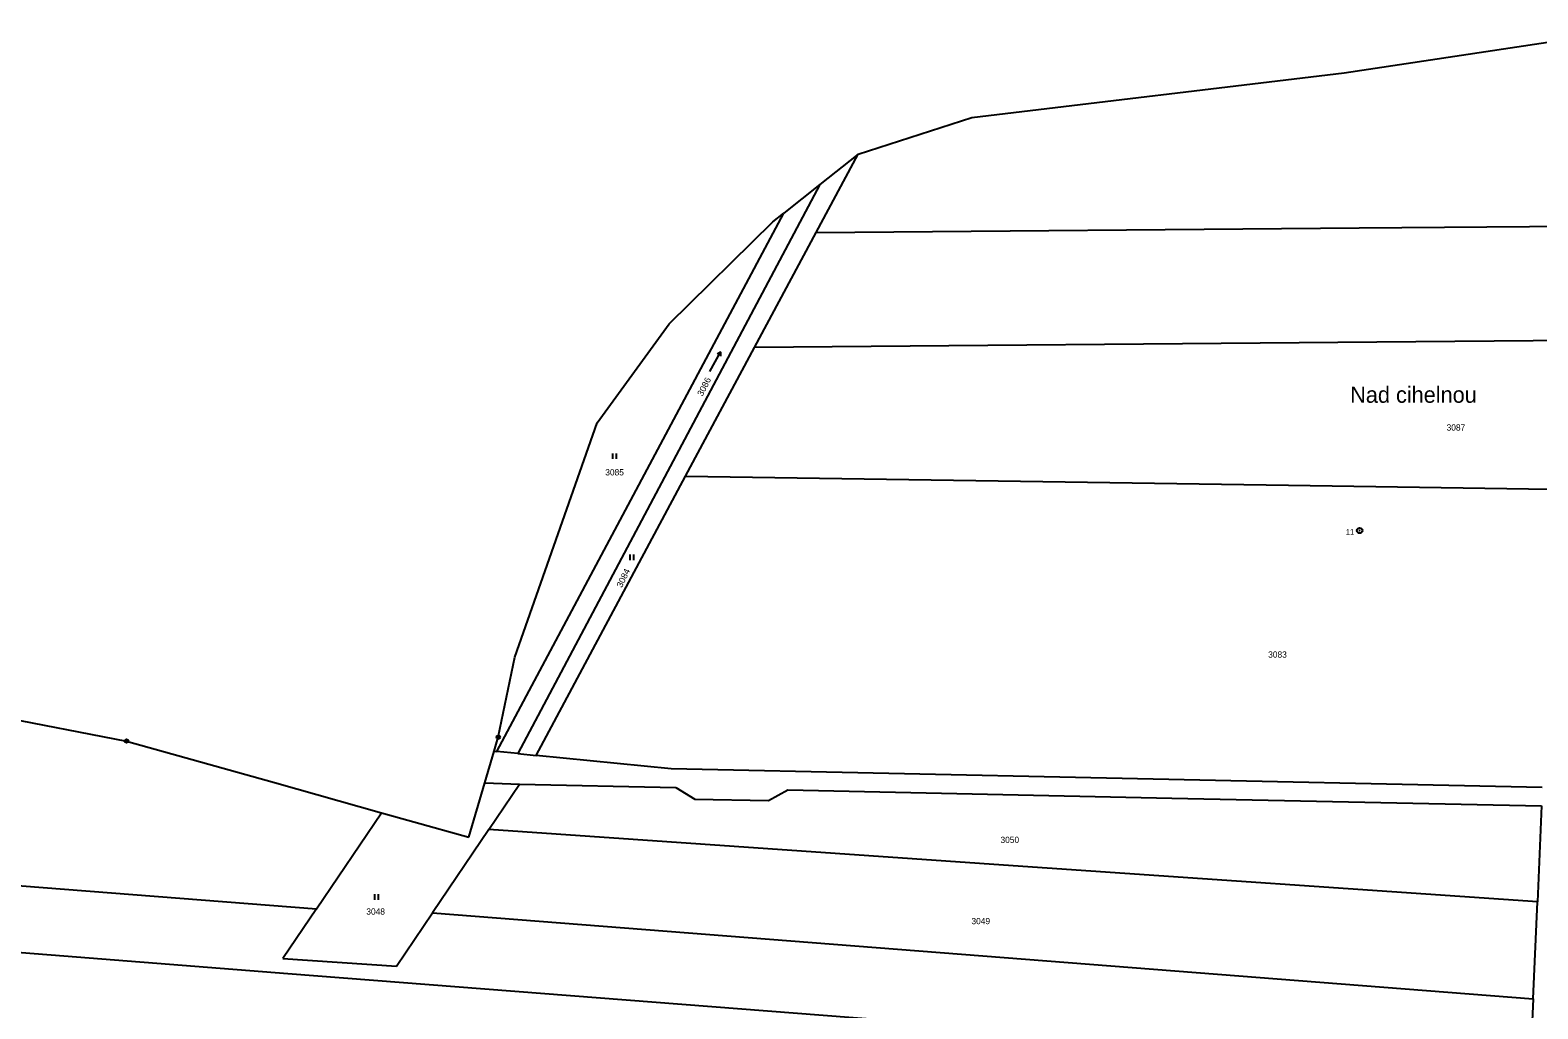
# Model space of a CAD drawing. Extents: x -618848 to -615803, y -1044450 to -1042254.
# Drawn here: x -617807.4 to -617398.4, y -1042588.2 to -1042322.9 of the extents above; entities that cross this region are included whole.
import ezdxf
from ezdxf.enums import TextEntityAlignment as Align

# ---------------------------------------------------------------- set-up
doc = ezdxf.new("R2010")
doc.units = 0
doc.header["$LTSCALE"] = 0.68
for name, color, linetype, lineweight in [('1', 7, 'Continuous', 25), ('3', 7, 'Continuous', 25), ('7', 7, 'Continuous', 13), ('8', 7, 'Continuous', 25)]:
    doc.layers.add(name, color=color, linetype=linetype, lineweight=lineweight)
doc.layers.add('2', color=7, linetype='Continuous')

msp = doc.modelspace()

# ---------------------------------------------------------------- linework, layer by layer
at = {"layer": '1'}
for p, q in [((-617450.93, -1042334.49), (-617374.17, -1042322.92)), ((-617551.92, -1042346.63), (-617450.93, -1042334.49)), ((-617582.79, -1042356.53), (-617551.92, -1042346.63)), ((-617594.16, -1042377.76), (-617582.79, -1042356.53)), ((-617582.79, -1042356.53), (-617593.16, -1042364.75)), ((-617593.16, -1042364.75), (-617675.07, -1042519.03)), ((-617593.16, -1042364.75), (-617602.93, -1042372.5)), ((-617680.74, -1042518.47), (-617602.93, -1042372.5)), ((-617634.06, -1042402.53), (-617605.92, -1042374.87)), ((-617605.92, -1042374.87), (-617602.93, -1042372.5)), ((-617446.82, -1042376.54), (-617299.47, -1042375.32)), ((-617610.87, -1042408.95), (-617594.16, -1042377.76)), ((-617594.16, -1042377.76), (-617446.82, -1042376.54)), ((-617653.53, -1042429.4), (-617634.06, -1042402.53)), ((-617442.07, -1042407.54), (-617610.87, -1042408.95)), ((-617273.27, -1042406.12), (-617442.07, -1042407.54)), ((-617629.57, -1042443.86), (-617610.87, -1042408.95)), ((-617675.87, -1042492.93), (-617653.53, -1042429.4)), ((-617670.1, -1042519.53), (-617629.57, -1042443.86)), ((-617629.57, -1042443.86), (-617465.98, -1042446.3)), ((-617465.98, -1042446.3), (-617302.39, -1042448.75)), ((-617680.4, -1042514.61), (-617675.87, -1042492.93)), ((-617817.51, -1042508.69), (-617781.23, -1042515.64)), ((-617681.51, -1042518.39), (-617680.4, -1042514.61)), ((-617781.23, -1042515.64), (-617741.09, -1042526.93)), ((-617684.03, -1042526.99), (-617681.51, -1042518.39)), ((-617681.51, -1042518.39), (-617680.74, -1042518.47)), ((-617675.07, -1042519.03), (-617680.74, -1042518.47)), ((-617675.07, -1042519.03), (-617670.1, -1042519.53)), ((-617633.48, -1042523.21), (-617670.1, -1042519.53)), ((-617741.09, -1042526.93), (-617712.05, -1042535.09)), ((-617688.36, -1042541.75), (-617684.03, -1042526.99)), ((-617684.03, -1042526.99), (-617674.61, -1042527.36)), ((-617515.35, -1042525.72), (-617633.48, -1042523.21)), ((-617397.22, -1042528.23), (-617515.35, -1042525.72)), ((-617682.92, -1042539.62), (-617674.61, -1042527.36)), ((-617674.61, -1042527.36), (-617632.2, -1042528.25)), ((-617632.2, -1042528.25), (-617627.06, -1042531.36)), ((-617607.08, -1042531.78), (-617601.82, -1042528.89)), ((-617601.82, -1042528.89), (-617497.67, -1042531.09)), ((-617497.67, -1042531.09), (-617397.33, -1042533.23)), ((-617729.69, -1042561.12), (-617712.05, -1042535.09)), ((-617712.05, -1042535.09), (-617703.27, -1042537.56)), ((-617627.06, -1042531.36), (-617607.08, -1042531.78)), ((-617397.33, -1042533.23), (-617398.46, -1042559.28)), ((-617703.27, -1042537.56), (-617688.36, -1042541.75)), ((-617682.92, -1042539.62), (-617698.22, -1042562.21)), ((-617540.69, -1042549.45), (-617682.92, -1042539.62)), ((-617890.38, -1042548.57), (-617729.69, -1042561.12)), ((-617398.46, -1042559.28), (-617540.69, -1042549.45)), ((-617399.62, -1042585.53), (-617398.46, -1042559.28)), ((-617729.69, -1042561.12), (-617738.79, -1042574.56)), ((-617708.01, -1042576.66), (-617698.22, -1042562.21)), ((-617698.22, -1042562.21), (-617548.92, -1042573.87)), ((-617737.45, -1042578.72), (-617905.93, -1042565.55)), ((-617738.79, -1042574.56), (-617708.01, -1042576.66)), ((-617548.92, -1042573.87), (-617399.62, -1042585.53)), ((-617568.98, -1042591.88), (-617737.45, -1042578.72)), ((-617399.62, -1042585.53), (-617400.5, -1042605.04))]:
    msp.add_line(p, q, dxfattribs=at)
at = {"layer": '3'}
for p, q in [((-617620.08, -1042410.185), (-617620.115, -1042411.283)), ((-617649.271, -1042439.17), (-617649.271, -1042437.67)), ((-617648.27, -1042439.17), (-617648.27, -1042437.67)), ((-617644.581, -1042466.59), (-617644.581, -1042465.09)), ((-617643.58, -1042466.59), (-617643.58, -1042465.09)), ((-617713.911, -1042558.68), (-617713.911, -1042557.18)), ((-617712.91, -1042558.68), (-617712.91, -1042557.18))]:
    msp.add_line(p, q, dxfattribs=at)
msp.add_lwpolyline([(-617622.989, -1042415.433), (-617620.08, -1042410.185), (-617620.992, -1042410.797)], dxfattribs=at)
at = {"layer": '8'}
for centre, radius in [((-617446.7, -1042458.5798), 0.75), ((-617446.7, -1042458.5798), 0.03), ((-617680.4, -1042514.6099), 0.5), ((-617680.4, -1042514.6099), 0.0303), ((-617781.23, -1042515.6399), 0.5), ((-617781.23, -1042515.6399), 0.0303)]:
    msp.add_circle(centre, radius, dxfattribs=at)

# ---------------------------------------------------------------- texts
at = {"layer": '2', "width": 1.05}
for s, rotation, p in [('3086', 63, (-617625.001, -1042422.312)), ('3084', 64, (-617646.878, -1042474.216))]:
    msp.add_text(s, height=1.7, rotation=rotation, dxfattribs=at).set_placement(p)
at = {"layer": '2'}
for s, p in [('3087', (-617423.11, -1042431.485)), ('3085', (-617651.36, -1042443.635)), ('3083', (-617471.52, -1042493.035)), ('3050', (-617544.14, -1042543.285)), ('3048', (-617716.19, -1042562.715)), ('3049', (-617552.02, -1042565.305))]:
    msp.add_text(s, height=1.7, dxfattribs=at).set_placement(p)
at = {"layer": '7'}
msp.add_text('Nad cihelnou', height=4.4, dxfattribs=at).set_placement((-617432.099, -1042423.94), align=Align.CENTER)
at = {"layer": '8'}
msp.add_text('11', height=1.5, dxfattribs=at).set_placement((-617448.199, -1042459.697), align=Align.RIGHT)

doc.saveas('drawing.dxf')
